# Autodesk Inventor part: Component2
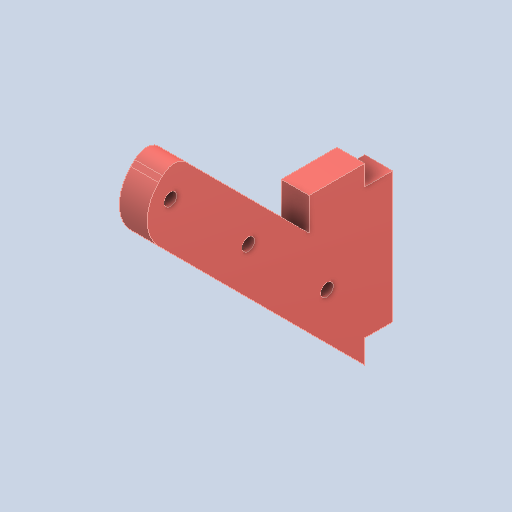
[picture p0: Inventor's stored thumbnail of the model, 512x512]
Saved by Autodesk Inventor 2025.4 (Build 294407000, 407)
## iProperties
Created: 2026-05
Part Number: Component2
Material: Generic
Document SubType Name: Modeling
Designer: AdminForWorker
Density: 1 g/cm^3
Appearance: Default
Title: Component2
Author: AdminForWorker
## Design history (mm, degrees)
feature "Body1"
body "Solid1"
